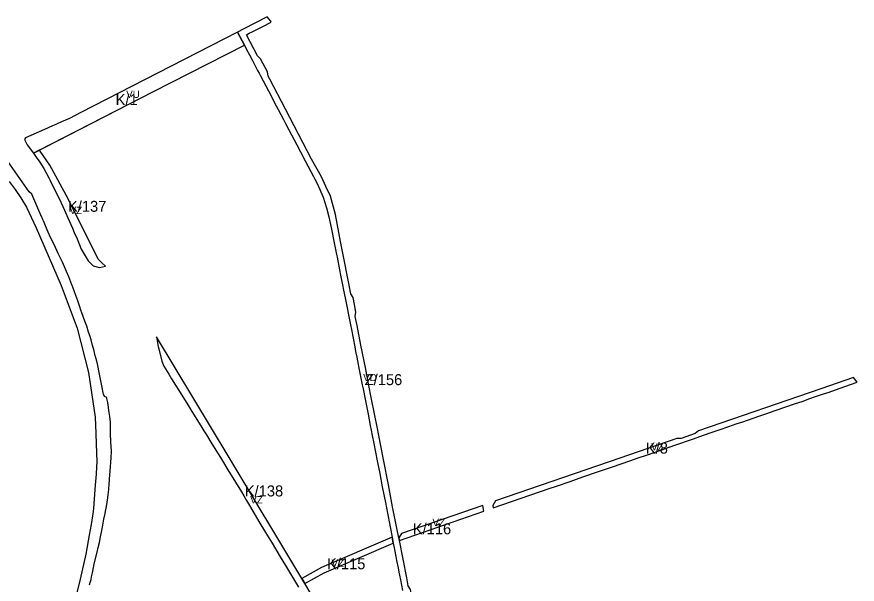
# Model space of a CAD drawing. Extents: x -521939 to -518034, y -1194984 to -1189555.
# Drawn here: x -520886 to -519738, y -1190331 to -1189555 of the extents above; entities that cross this region are included whole.
import ezdxf

# ---------------------------------------------------------------- set-up
doc = ezdxf.new("R2010")
doc.units = 0
for name, color, linetype in [('95420023', 7, 'Continuous'), ('96111023', 7, 'Continuous'), ('96121023', 7, 'Continuous'), ('96141023', 7, 'Continuous'), ('96202223', 7, 'Continuous')]:
    doc.layers.add(name, color=color, linetype=linetype)

msp = doc.modelspace()

# ---------------------------------------------------------------- linework, layer by layer
at = {"layer": '95420023'}
for points in [[(-520363.78, -1190267.42), (-520366.37, -1190254.23), (-520372.66, -1190225.12), (-520377.99, -1190195.02), (-520384.87, -1190160.07), (-520391.56, -1190125.16), (-520393.2, -1190117.89), (-520397.27, -1190097.65), (-520401.22, -1190077.65), (-520405.21, -1190056.77), (-520409.61, -1190034.24), (-520415.58, -1190003.82), (-520420.88, -1189976.82), (-520423.3, -1189964.53), (-520422.41, -1189958.68), (-520424.49, -1189948.09), (-520426.3, -1189938.88), (-520429.34, -1189933.8), (-520431.66, -1189922.07), (-520433.46, -1189912.89), (-520438.94, -1189885.01), (-520443.42, -1189862.15), (-520450.25, -1189825.06), (-520457.28, -1189799.95), (-520463.47, -1189786.79), (-520469.68, -1189773.95), (-520483.13, -1189749.49), (-520518.67, -1189681.41), (-520540.29, -1189640.25), (-520542.46, -1189636.12), (-520543.28, -1189630.26), (-520552.66, -1189612.4), (-520557.02, -1189608.4), (-520572.14, -1189579.59), (-520568.14, -1189577.53), (-520564.14, -1189575.47), (-520555.14, -1189570.83), (-520546.14, -1189566.2), (-520542.1, -1189564.12), (-520538.07, -1189562.04), (-520538.7, -1189561.06), (-520543.9, -1189554.92), (-520576.33, -1189571.62), (-520584.33, -1189575.74)], [(-520584.33, -1189575.74), (-520574.91, -1189593.69)], [(-520574.91, -1189593.69), (-520571.87, -1189599.49), (-520567.98, -1189606.88), (-520563.29, -1189615.69), (-520556.78, -1189628.12), (-520554.77, -1189631.94), (-520552.78, -1189635.77), (-520542.06, -1189656.2), (-520536.5, -1189666.75), (-520533.97, -1189671.56), (-520528.55, -1189681.89), (-520521.58, -1189695.28), (-520518.55, -1189700.78), (-520513.98, -1189709.68), (-520506.96, -1189723.04), (-520503.29, -1189730.03), (-520498.25, -1189739.55), (-520491.89, -1189751.79), (-520480.47, -1189773.36), (-520478.5, -1189777.12), (-520474.96, -1189783.97), (-520467.22, -1189801.74), (-520462.52, -1189816.05), (-520459.4, -1189828.36), (-520457.93, -1189834.89), (-520455.88, -1189845.31), (-520452.13, -1189864.14), (-520448.96, -1189880.06), (-520448.32, -1189883.37), (-520444.85, -1189900.94), (-520443.47, -1189908.13), (-520440.81, -1189921.53), (-520439.37, -1189928.74), (-520437.33, -1189939.01), (-520429.98, -1189976.03), (-520428.73, -1189982.35), (-520424.06, -1190006.15), (-520422.85, -1190012.32), (-520421.24, -1190020.5), (-520418.36, -1190035.16), (-520413.93, -1190058), (-520412.81, -1190063.42), (-520409.99, -1190077.75), (-520405.98, -1190098.21), (-520402.94, -1190113.68), (-520401.68, -1190120.11), (-520400.22, -1190127.57), (-520398.08, -1190138.46), (-520393.44, -1190162.05), (-520389.99, -1190179.56), (-520386.49, -1190197.4), (-520382.22, -1190219.18), (-520379.42, -1190233.48), (-520372.97, -1190266.32)], [(-520868.84, -1189794.27), (-520900.54, -1189748.5)], [(-520896.35, -1189780.16), (-520887.88, -1189790.95), (-520880.21, -1189802.32), (-520872.55, -1189815.19), (-520859.28, -1189843.65), (-520825.3, -1189922.44), (-520803.36, -1189980.65), (-520787.67, -1190041.34), (-520778.83, -1190102.4), (-520777.95, -1190124.57)], [(-520762.83, -1190075.3), (-520766.02, -1190074.02), (-520767.55, -1190070.93), (-520767.88, -1190069.17), (-520769.27, -1190061.72), (-520770.98, -1190052.51), (-520773.22, -1190041.38), (-520775.2, -1190031.58), (-520776.66, -1190025.8), (-520777.88, -1190020.97), (-520778.96, -1190016.65), (-520779.7, -1190013.73), (-520780.76, -1190009.83), (-520782.34, -1190004.2), (-520784.38, -1189996.52), (-520784.78, -1189995.03), (-520785.69, -1189992.16), (-520787.64, -1189985.97), (-520790.16, -1189978), (-520792.63, -1189971.08), (-520794.56, -1189965.83), (-520797.3, -1189958.38), (-520797.68, -1189957.29), (-520800.24, -1189949.98), (-520802.52, -1189943.48), (-520803.82, -1189939.77), (-520805.23, -1189935.82), (-520807.51, -1189929.41), (-520810.03, -1189922.31), (-520810.37, -1189921.35), (-520814.9, -1189910.36), (-520817.79, -1189903.36), (-520820.8, -1189896.58), (-520823.49, -1189890.54), (-520825.65, -1189885.69), (-520829.04, -1189878.62), (-520832.97, -1189870.44), (-520835.85, -1189864.43), (-520839.61, -1189856.58), (-520843.01, -1189849.46), (-520846.54, -1189840.93), (-520849.51, -1189833.76), (-520850.55, -1189831.25), (-520852.17, -1189827.72), (-520852.36, -1189827.29), (-520854.03, -1189823.64), (-520854.32, -1189823.02), (-520865.38, -1189797.27), (-520868.84, -1189794.27)], [(-520762.61, -1190076.58), (-520762.83, -1190075.3)], [(-520760.63, -1190088.46), (-520761.63, -1190082.43), (-520762.61, -1190076.58)], [(-520760.42, -1190089.68), (-520760.63, -1190088.46)], [(-520757.75, -1190120.86), (-520757.85, -1190109.85), (-520757.85, -1190109.21), (-520758.86, -1190101.6), (-520759.61, -1190095.86), (-520760.42, -1190089.68)], [(-520777.95, -1190124.57), (-520777.29, -1190138.74)], [(-520757.68, -1190128.9), (-520757.7, -1190126.98), (-520757.75, -1190120.86)], [(-520756.81, -1190142.53), (-520757.19, -1190136.49), (-520757.5, -1190131.72), (-520757.68, -1190128.9)], [(-520777.29, -1190138.74), (-520776.47, -1190163.36), (-520776.83, -1190170.44)], [(-520756.42, -1190148.49), (-520756.81, -1190142.53)], [(-520756.5, -1190149.9), (-520756.42, -1190148.49)], [(-520757.3, -1190164.53), (-520756.9, -1190157.22)], [(-520756.9, -1190157.22), (-520756.5, -1190149.9)], [(-520776.83, -1190170.44), (-520777.49, -1190180.07)], [(-520758.55, -1190180.97), (-520758.15, -1190176.09), (-520757.6, -1190169.44)], [(-520757.6, -1190169.44), (-520757.3, -1190164.53)], [(-520777.49, -1190180.07), (-520778.53, -1190195.44)], [(-520759.12, -1190187.87), (-520759.06, -1190187.22), (-520758.55, -1190180.97)], [(-520778.53, -1190195.44), (-520780.79, -1190226.94)], [(-520760.72, -1190205.7), (-520760.23, -1190200.24), (-520759.65, -1190193.81)], [(-520759.65, -1190193.81), (-520759.12, -1190187.87)], [(-520760.87, -1190207.48), (-520760.72, -1190205.7)], [(-520765.22, -1190234.17), (-520763.96, -1190228.21), (-520763.7, -1190226.98), (-520762.5, -1190218.73), (-520761.63, -1190212.72), (-520760.87, -1190207.48)], [(-520780.79, -1190226.94), (-520781.3, -1190231.43)], [(-520781.3, -1190231.43), (-520784.36, -1190249.11)], [(-520766.85, -1190241.85), (-520765.22, -1190234.17)], [(-520784.36, -1190249.11), (-520786.83, -1190263.81)], [(-520773, -1190273.46), (-520771.25, -1190266.04), (-520769.69, -1190257.16), (-520768.43, -1190249.96), (-520766.85, -1190241.85)], [(-520786.83, -1190263.81), (-520791.44, -1190289.68)], [(-520776.16, -1190286.78), (-520774.67, -1190280.5), (-520773, -1190273.46)], [(-520372.97, -1190266.32), (-520371.58, -1190274.42)], [(-520371.58, -1190274.42), (-520369.76, -1190283.42), (-520368, -1190292.59), (-520366.87, -1190298.24), (-520364.88, -1190308.35), (-520363.75, -1190314.16), (-520362.96, -1190318.16), (-520361.67, -1190324.78), (-520358.8, -1190339.19)], [(-520363.12, -1190270.76), (-520363.78, -1190267.42)], [(-520260.36, -1190640.4), (-520246.6, -1190614.37), (-520254.03, -1190602.44), (-520256.94, -1190586.97), (-520261.73, -1190576.17), (-520292.37, -1190520.37), (-520305.38, -1190497.4), (-520313.7, -1190481.31), (-520322.01, -1190463.84), (-520328.19, -1190444.19), (-520333.62, -1190421.51), (-520339.48, -1190390.73), (-520343.5, -1190372.52), (-520344.85, -1190363.88), (-520343.97, -1190357.86), (-520345.06, -1190352.29), (-520347.86, -1190338.07), (-520350.9, -1190332.99), (-520352.86, -1190322.18), (-520363.12, -1190270.76)], [(-520780.71, -1190305.7), (-520780.47, -1190304.54), (-520776.16, -1190286.78)], [(-520791.44, -1190289.68), (-520799.14, -1190323.82)], [(-520784.38, -1190324.15), (-520783.68, -1190320.65), (-520782.55, -1190314.95), (-520780.71, -1190305.7)], [(-520799.14, -1190323.82), (-520803.11, -1190340.79), (-520817.75, -1190406.02)], [(-520786.36, -1190331.78), (-520785.46, -1190328.32)], [(-520785.46, -1190328.32), (-520784.38, -1190324.15)]]:
    msp.add_lwpolyline(points, dxfattribs=at)
at = {"layer": '96111023'}
for points in [[(-520584.33, -1189575.74), (-520693.52, -1189631.98), (-520798.15, -1189685.87)], [(-520574.91, -1189593.69), (-520584.33, -1189575.74)], [(-520862.97, -1189741.45), (-520698.86, -1189657.27), (-520574.91, -1189593.69)], [(-520798.15, -1189685.87), (-520813.62, -1189693.84)], [(-520831.59, -1189701.76), (-520832.44, -1189702.13)], [(-520824.7, -1189698.73), (-520831.59, -1189701.76)], [(-520813.62, -1189693.84), (-520824.7, -1189698.73)], [(-520848.1, -1189709.03), (-520873.85, -1189720.38)], [(-520836.95, -1189704.12), (-520848.1, -1189709.03)], [(-520832.44, -1189702.13), (-520836.95, -1189704.12)], [(-520873.85, -1189720.38), (-520875.18, -1189722.65)], [(-520875.18, -1189722.65), (-520871.46, -1189729.85)], [(-520871.46, -1189729.85), (-520862.97, -1189741.45)], [(-520855.05, -1189737.39), (-520862.97, -1189741.45)], [(-520862.97, -1189741.45), (-520859.09, -1189746.74)], [(-520859.09, -1189746.74), (-520854.49, -1189753.78)], [(-520854.52, -1189738.05), (-520855.05, -1189737.39)], [(-520769.62, -1189891.18), (-520774.69, -1189886.48), (-520815.47, -1189803.6), (-520840.73, -1189757.97), (-520853.99, -1189738.71), (-520854.52, -1189738.05)], [(-520854.49, -1189753.78), (-520848.98, -1189762.26)], [(-520848.98, -1189762.26), (-520842.22, -1189775.08)], [(-520842.22, -1189775.08), (-520840.25, -1189778.89)], [(-520840.25, -1189778.89), (-520838.28, -1189782.7)], [(-520838.28, -1189782.7), (-520827.89, -1189803.41)], [(-520827.89, -1189803.41), (-520822.82, -1189814.19)], [(-520822.82, -1189814.19), (-520820.55, -1189819.14)], [(-520820.55, -1189819.14), (-520815.85, -1189829.79)], [(-520815.85, -1189829.79), (-520809.87, -1189843.72)], [(-520809.87, -1189843.72), (-520807.32, -1189849.61)], [(-520807.32, -1189849.61), (-520803.4, -1189858.68)], [(-520803.4, -1189858.68), (-520797.65, -1189872.73)], [(-520797.65, -1189872.73), (-520793.8, -1189879.57)], [(-520793.8, -1189879.57), (-520788.07, -1189888.65)], [(-520788.07, -1189888.65), (-520785.91, -1189890.86)], [(-520785.91, -1189890.86), (-520781.3, -1189895.57), (-520772.63, -1189897.76), (-520764.56, -1189895.88)], [(-520764.56, -1189895.88), (-520769.62, -1189891.18)], [(-520595.57, -1190157.59), (-520694.98, -1189992.45)], [(-520694.98, -1189992.45), (-520692.55, -1190005.5)], [(-520692.55, -1190005.5), (-520691.84, -1190008.79)], [(-520691.84, -1190008.79), (-520687.51, -1190025.96)], [(-520687.51, -1190025.96), (-520685.06, -1190032.49)], [(-520685.06, -1190032.49), (-520678.04, -1190043.73)], [(-520678.04, -1190043.73), (-520674.3, -1190049.78)], [(-520674.3, -1190049.78), (-520668.96, -1190058.36)], [(-519742.92, -1190048.01), (-519787.45, -1190063.39), (-519954.51, -1190121.09), (-519959.21, -1190124.83), (-519978.27, -1190131.41), (-519984.27, -1190131.37), (-520061.95, -1190158.2), (-520231.96, -1190216.92), (-520235.61, -1190223.15)], [(-519762.5, -1190063.2), (-519737.67, -1190054.66)], [(-519737.67, -1190054.66), (-519742.92, -1190048.01)], [(-520668.96, -1190058.36), (-520664.99, -1190064.75), (-520649.81, -1190089.25)], [(-519785.22, -1190071.01), (-519776.17, -1190067.93)], [(-519776.17, -1190067.93), (-519762.5, -1190063.2)], [(-519821.87, -1190083.74), (-519813.04, -1190080.72)], [(-519813.04, -1190080.72), (-519802.38, -1190076.99)], [(-519802.38, -1190076.99), (-519794.41, -1190074.26)], [(-519794.41, -1190074.26), (-519785.22, -1190071.01)], [(-520649.81, -1190089.25), (-520646.54, -1190094.49)], [(-519849.58, -1190093.29), (-519821.87, -1190083.74)], [(-520646.54, -1190094.49), (-520634.26, -1190114.38)], [(-519893.94, -1190108.6), (-519871.89, -1190101.04)], [(-519871.89, -1190101.04), (-519862.6, -1190097.78)], [(-519862.6, -1190097.78), (-519849.58, -1190093.29)], [(-520634.26, -1190114.38), (-520630.08, -1190121.08)], [(-519913.25, -1190115.28), (-519903.02, -1190111.63)], [(-519903.02, -1190111.63), (-519893.94, -1190108.6)], [(-520630.08, -1190121.08), (-520626.81, -1190126.38)], [(-520626.81, -1190126.38), (-520619.25, -1190138.59)], [(-519962.62, -1190132.36), (-519946.2, -1190126.69)], [(-519946.2, -1190126.69), (-519936.96, -1190123.44)], [(-519936.96, -1190123.44), (-519926.15, -1190119.68)], [(-519926.15, -1190119.68), (-519913.25, -1190115.28)], [(-519986.68, -1190140.64), (-519962.62, -1190132.36)], [(-520619.25, -1190138.59), (-520607.45, -1190157.65)], [(-520013.6, -1190149.97), (-519986.68, -1190140.64)], [(-520607.45, -1190157.65), (-520604.7, -1190162.17)], [(-520492.06, -1190329.61), (-520496.15, -1190322.74), (-520595.57, -1190157.59)], [(-520048.21, -1190161.91), (-520036.77, -1190157.93)], [(-520036.77, -1190157.93), (-520024.36, -1190153.64)], [(-520024.36, -1190153.64), (-520013.6, -1190149.97)], [(-520604.7, -1190162.17), (-520597.31, -1190174.18)], [(-520092.49, -1190177.21), (-520071.81, -1190170.12)], [(-520071.81, -1190170.12), (-520060.18, -1190166.05), (-520048.21, -1190161.91)], [(-520597.31, -1190174.18), (-520586.78, -1190191.32)], [(-520129.95, -1190190.13), (-520112.49, -1190184.08)], [(-520112.49, -1190184.08), (-520092.49, -1190177.21)], [(-520586.78, -1190191.32), (-520578.85, -1190204.26)], [(-520148.48, -1190196.56), (-520129.95, -1190190.13)], [(-520578.85, -1190204.26), (-520575.54, -1190209.65)], [(-520235.01, -1190226.44), (-520158.52, -1190200.01)], [(-520158.52, -1190200.01), (-520148.48, -1190196.56)], [(-520575.54, -1190209.65), (-520571.92, -1190216.03)], [(-520571.92, -1190216.03), (-520566.46, -1190225.16)], [(-520566.46, -1190225.16), (-520555.01, -1190244.86)], [(-520249.16, -1190222.86), (-520360.13, -1190261.18), (-520363.78, -1190267.42)], [(-520247.81, -1190230.86), (-520249.16, -1190222.86)], [(-520235.61, -1190223.15), (-520235.01, -1190226.44)], [(-520363.12, -1190270.76), (-520247.81, -1190230.86)], [(-520555.01, -1190244.86), (-520546, -1190259.94)], [(-520546, -1190259.94), (-520537.12, -1190274.8)], [(-520537.12, -1190274.8), (-520525.87, -1190293.08)], [(-520372.97, -1190266.32), (-520469.39, -1190307.83)], [(-520465.85, -1190315.02), (-520371.58, -1190274.42)], [(-520371.58, -1190274.42), (-520372.97, -1190266.32)], [(-520363.78, -1190267.42), (-520363.12, -1190270.76)], [(-520525.87, -1190293.08), (-520518.77, -1190305.18)], [(-520518.77, -1190305.18), (-520505.06, -1190327.7)], [(-520469.39, -1190307.83), (-520496.15, -1190322.74)], [(-520492.06, -1190329.61), (-520465.85, -1190315.02)], [(-520505.06, -1190327.7), (-520500.89, -1190334.53)], [(-520496.15, -1190322.74), (-520492.06, -1190329.61)], [(-520418.63, -1190454.51), (-520492.06, -1190329.61)]]:
    msp.add_lwpolyline(points, dxfattribs=at)
at = {"layer": '96121023'}
for points in [[(-520363.78, -1190267.42), (-520366.37, -1190254.23), (-520372.66, -1190225.12), (-520377.99, -1190195.02), (-520384.87, -1190160.07), (-520391.56, -1190125.16), (-520393.2, -1190117.89), (-520397.27, -1190097.65), (-520401.22, -1190077.65), (-520405.21, -1190056.77), (-520409.61, -1190034.24), (-520415.58, -1190003.82), (-520420.88, -1189976.82), (-520423.3, -1189964.53), (-520422.41, -1189958.68), (-520424.49, -1189948.09), (-520426.3, -1189938.88), (-520429.34, -1189933.8), (-520431.66, -1189922.07), (-520433.46, -1189912.89), (-520438.94, -1189885.01), (-520443.42, -1189862.15), (-520450.25, -1189825.06), (-520457.28, -1189799.95), (-520463.47, -1189786.79), (-520469.68, -1189773.95), (-520483.13, -1189749.49), (-520518.67, -1189681.41), (-520540.29, -1189640.25), (-520542.46, -1189636.12), (-520543.28, -1189630.26), (-520552.66, -1189612.4), (-520557.02, -1189608.4), (-520572.14, -1189579.59), (-520568.14, -1189577.53), (-520564.14, -1189575.47), (-520555.14, -1189570.83), (-520546.14, -1189566.2), (-520542.1, -1189564.12), (-520538.07, -1189562.04), (-520538.7, -1189561.06), (-520543.9, -1189554.92), (-520576.33, -1189571.62), (-520584.33, -1189575.74)], [(-520584.33, -1189575.74), (-520574.91, -1189593.69)], [(-520574.91, -1189593.69), (-520571.87, -1189599.49), (-520567.98, -1189606.88), (-520563.29, -1189615.69), (-520556.78, -1189628.12), (-520554.77, -1189631.94), (-520552.78, -1189635.77), (-520542.06, -1189656.2), (-520536.5, -1189666.75), (-520533.97, -1189671.56), (-520528.55, -1189681.89), (-520521.58, -1189695.28), (-520518.55, -1189700.78), (-520513.98, -1189709.68), (-520506.96, -1189723.04), (-520503.29, -1189730.03), (-520498.25, -1189739.55), (-520491.89, -1189751.79), (-520480.47, -1189773.36), (-520478.5, -1189777.12), (-520474.96, -1189783.97), (-520467.22, -1189801.74), (-520462.52, -1189816.05), (-520459.4, -1189828.36), (-520457.93, -1189834.89), (-520455.88, -1189845.31), (-520452.13, -1189864.14), (-520448.96, -1189880.06), (-520448.32, -1189883.37), (-520444.85, -1189900.94), (-520443.47, -1189908.13), (-520440.81, -1189921.53), (-520439.37, -1189928.74), (-520437.33, -1189939.01), (-520429.98, -1189976.03), (-520428.73, -1189982.35), (-520424.06, -1190006.15), (-520422.85, -1190012.32), (-520421.24, -1190020.5), (-520418.36, -1190035.16), (-520413.93, -1190058), (-520412.81, -1190063.42), (-520409.99, -1190077.75), (-520405.98, -1190098.21), (-520402.94, -1190113.68), (-520401.68, -1190120.11), (-520400.22, -1190127.57), (-520398.08, -1190138.46), (-520393.44, -1190162.05), (-520389.99, -1190179.56), (-520386.49, -1190197.4), (-520382.22, -1190219.18), (-520379.42, -1190233.48), (-520372.97, -1190266.32)], [(-520372.97, -1190266.32), (-520371.58, -1190274.42)], [(-520371.58, -1190274.42), (-520369.76, -1190283.42), (-520368, -1190292.59), (-520366.87, -1190298.24), (-520364.88, -1190308.35), (-520363.75, -1190314.16), (-520362.96, -1190318.16), (-520361.67, -1190324.78), (-520358.8, -1190339.19)], [(-520363.12, -1190270.76), (-520363.78, -1190267.42)], [(-520260.36, -1190640.4), (-520246.6, -1190614.37), (-520254.03, -1190602.44), (-520256.94, -1190586.97), (-520261.73, -1190576.17), (-520292.37, -1190520.37), (-520305.38, -1190497.4), (-520313.7, -1190481.31), (-520322.01, -1190463.84), (-520328.19, -1190444.19), (-520333.62, -1190421.51), (-520339.48, -1190390.73), (-520343.5, -1190372.52), (-520344.85, -1190363.88), (-520343.97, -1190357.86), (-520345.06, -1190352.29), (-520347.86, -1190338.07), (-520350.9, -1190332.99), (-520352.86, -1190322.18), (-520363.12, -1190270.76)]]:
    msp.add_lwpolyline(points, dxfattribs=at)
at = {"layer": '96141023'}
for points in [[(-520584.33, -1189575.74), (-520693.52, -1189631.98), (-520798.15, -1189685.87)], [(-520574.91, -1189593.69), (-520584.33, -1189575.74)], [(-520855.05, -1189737.39), (-520698.86, -1189657.27), (-520574.91, -1189593.69)], [(-520798.15, -1189685.87), (-520813.62, -1189693.84)], [(-520831.59, -1189701.76), (-520832.44, -1189702.13)], [(-520824.7, -1189698.73), (-520831.59, -1189701.76)], [(-520813.62, -1189693.84), (-520824.7, -1189698.73)], [(-520848.1, -1189709.03), (-520873.85, -1189720.38)], [(-520836.95, -1189704.12), (-520848.1, -1189709.03)], [(-520832.44, -1189702.13), (-520836.95, -1189704.12)], [(-520873.85, -1189720.38), (-520875.18, -1189722.65)], [(-520875.18, -1189722.65), (-520871.46, -1189729.85)], [(-520871.46, -1189729.85), (-520862.97, -1189741.45)], [(-520862.97, -1189741.45), (-520855.05, -1189737.39)]]:
    msp.add_lwpolyline(points, dxfattribs=at)
at = {"layer": '96202223'}
for points in [[(-520855.05, -1189737.39), (-520862.97, -1189741.45)], [(-520862.97, -1189741.45), (-520859.09, -1189746.74)], [(-520859.09, -1189746.74), (-520854.49, -1189753.78)], [(-520854.52, -1189738.05), (-520855.05, -1189737.39)], [(-520769.62, -1189891.18), (-520774.69, -1189886.48), (-520815.47, -1189803.6), (-520840.73, -1189757.97), (-520853.99, -1189738.71), (-520854.52, -1189738.05)], [(-520854.49, -1189753.78), (-520848.98, -1189762.26)], [(-520848.98, -1189762.26), (-520842.22, -1189775.08)], [(-520842.22, -1189775.08), (-520840.25, -1189778.89)], [(-520840.25, -1189778.89), (-520838.28, -1189782.7)], [(-520838.28, -1189782.7), (-520827.89, -1189803.41)], [(-520827.89, -1189803.41), (-520822.82, -1189814.19)], [(-520822.82, -1189814.19), (-520820.55, -1189819.14)], [(-520820.55, -1189819.14), (-520815.85, -1189829.79)], [(-520815.85, -1189829.79), (-520809.87, -1189843.72)], [(-520809.87, -1189843.72), (-520807.32, -1189849.61)], [(-520807.32, -1189849.61), (-520803.4, -1189858.68)], [(-520803.4, -1189858.68), (-520797.65, -1189872.73)], [(-520797.65, -1189872.73), (-520793.8, -1189879.57)], [(-520793.8, -1189879.57), (-520788.07, -1189888.65)], [(-520788.07, -1189888.65), (-520785.91, -1189890.86)], [(-520785.91, -1189890.86), (-520781.3, -1189895.57), (-520772.63, -1189897.76), (-520764.56, -1189895.88)], [(-520764.56, -1189895.88), (-520769.62, -1189891.18)], [(-520595.57, -1190157.59), (-520694.98, -1189992.45)], [(-520694.98, -1189992.45), (-520692.55, -1190005.5)], [(-520692.55, -1190005.5), (-520691.84, -1190008.79)], [(-520691.84, -1190008.79), (-520687.51, -1190025.96)], [(-520687.51, -1190025.96), (-520685.06, -1190032.49)], [(-520685.06, -1190032.49), (-520678.04, -1190043.73)], [(-520678.04, -1190043.73), (-520674.3, -1190049.78)], [(-520674.3, -1190049.78), (-520668.96, -1190058.36)], [(-519742.92, -1190048.01), (-519787.45, -1190063.39), (-519954.51, -1190121.09), (-519959.21, -1190124.83), (-519978.27, -1190131.41), (-519984.27, -1190131.37), (-520061.95, -1190158.2), (-520231.96, -1190216.92), (-520235.61, -1190223.15)], [(-519762.5, -1190063.2), (-519737.67, -1190054.66)], [(-519737.67, -1190054.66), (-519742.92, -1190048.01)], [(-520668.96, -1190058.36), (-520664.99, -1190064.75), (-520649.81, -1190089.25)], [(-519785.22, -1190071.01), (-519776.17, -1190067.93)], [(-519776.17, -1190067.93), (-519762.5, -1190063.2)], [(-519821.87, -1190083.74), (-519813.04, -1190080.72)], [(-519813.04, -1190080.72), (-519802.38, -1190076.99)], [(-519802.38, -1190076.99), (-519794.41, -1190074.26)], [(-519794.41, -1190074.26), (-519785.22, -1190071.01)], [(-520649.81, -1190089.25), (-520646.54, -1190094.49)], [(-519849.58, -1190093.29), (-519821.87, -1190083.74)], [(-520646.54, -1190094.49), (-520634.26, -1190114.38)], [(-519893.94, -1190108.6), (-519871.89, -1190101.04)], [(-519871.89, -1190101.04), (-519862.6, -1190097.78)], [(-519862.6, -1190097.78), (-519849.58, -1190093.29)], [(-520634.26, -1190114.38), (-520630.08, -1190121.08)], [(-519913.25, -1190115.28), (-519903.02, -1190111.63)], [(-519903.02, -1190111.63), (-519893.94, -1190108.6)], [(-520630.08, -1190121.08), (-520626.81, -1190126.38)], [(-520626.81, -1190126.38), (-520619.25, -1190138.59)], [(-519962.62, -1190132.36), (-519946.2, -1190126.69)], [(-519946.2, -1190126.69), (-519936.96, -1190123.44)], [(-519936.96, -1190123.44), (-519926.15, -1190119.68)], [(-519926.15, -1190119.68), (-519913.25, -1190115.28)], [(-519986.68, -1190140.64), (-519962.62, -1190132.36)], [(-520619.25, -1190138.59), (-520607.45, -1190157.65)], [(-520013.6, -1190149.97), (-519986.68, -1190140.64)], [(-520607.45, -1190157.65), (-520604.7, -1190162.17)], [(-520496.15, -1190322.74), (-520595.57, -1190157.59)], [(-520048.21, -1190161.91), (-520036.77, -1190157.93)], [(-520036.77, -1190157.93), (-520024.36, -1190153.64)], [(-520024.36, -1190153.64), (-520013.6, -1190149.97)], [(-520604.7, -1190162.17), (-520597.31, -1190174.18)], [(-520092.49, -1190177.21), (-520071.81, -1190170.12)], [(-520071.81, -1190170.12), (-520060.18, -1190166.05), (-520048.21, -1190161.91)], [(-520597.31, -1190174.18), (-520586.78, -1190191.32)], [(-520129.95, -1190190.13), (-520112.49, -1190184.08)], [(-520112.49, -1190184.08), (-520092.49, -1190177.21)], [(-520586.78, -1190191.32), (-520578.85, -1190204.26)], [(-520148.48, -1190196.56), (-520129.95, -1190190.13)], [(-520578.85, -1190204.26), (-520575.54, -1190209.65)], [(-520235.01, -1190226.44), (-520158.52, -1190200.01)], [(-520158.52, -1190200.01), (-520148.48, -1190196.56)], [(-520575.54, -1190209.65), (-520571.92, -1190216.03)], [(-520571.92, -1190216.03), (-520566.46, -1190225.16)], [(-520566.46, -1190225.16), (-520555.01, -1190244.86)], [(-520249.16, -1190222.86), (-520360.13, -1190261.18), (-520363.78, -1190267.42)], [(-520247.81, -1190230.86), (-520249.16, -1190222.86)], [(-520235.61, -1190223.15), (-520235.01, -1190226.44)], [(-520363.12, -1190270.76), (-520247.81, -1190230.86)], [(-520555.01, -1190244.86), (-520546, -1190259.94)], [(-520546, -1190259.94), (-520537.12, -1190274.8)], [(-520537.12, -1190274.8), (-520525.87, -1190293.08)], [(-520372.97, -1190266.32), (-520469.39, -1190307.83)], [(-520465.85, -1190315.02), (-520371.58, -1190274.42)], [(-520371.58, -1190274.42), (-520372.97, -1190266.32)], [(-520363.78, -1190267.42), (-520363.12, -1190270.76)], [(-520525.87, -1190293.08), (-520518.77, -1190305.18)], [(-520518.77, -1190305.18), (-520505.06, -1190327.7)], [(-520469.39, -1190307.83), (-520496.15, -1190322.74)], [(-520492.06, -1190329.61), (-520465.85, -1190315.02)], [(-520505.06, -1190327.7), (-520500.89, -1190334.53)], [(-520492.06, -1190329.61), (-520496.15, -1190322.74)], [(-520496.15, -1190322.74), (-520492.06, -1190329.61)], [(-520418.63, -1190454.51), (-520492.06, -1190329.61)]]:
    msp.add_lwpolyline(points, dxfattribs=at)

# ---------------------------------------------------------------- texts
at = {"layer": '95420023'}
msp.add_text('Z/156', height=15, rotation=0, dxfattribs=at).set_placement((-520410.49, -1190058.54))
at = {"layer": '96111023'}
for s, rotation, p in [('K/1', 0, (-520750.79, -1189675.67)), ('K/137', 0, (-520815.85, -1189821.56)), ('K/8', 360, (-520026.37, -1190152.09)), ('K/138', 360, (-520574.25, -1190210.71)), ('K/116', 360, (-520344.77, -1190262.44)), ('K/115', 360, (-520461.97, -1190310.22))]:
    msp.add_text(s, height=15, rotation=rotation, dxfattribs=at).set_placement(p)
at = {"layer": '96121023'}
msp.add_text('VD', height=10, rotation=360, dxfattribs=at).set_placement((-520412.62, -1190053.09))
at = {"layer": '96141023'}
msp.add_text('VU', height=10, rotation=0, dxfattribs=at).set_placement((-520736.29, -1189665.78))
at = {"layer": '96202223'}
for rotation, p in [(0, (-520813.66, -1189824.73)), (360, (-520019.16, -1190147.89)), (0, (-520317.94, -1190251.25)), (0, (-520455.92, -1190306.81))]:
    msp.add_text('VZ', height=10, rotation=rotation, dxfattribs=at).set_placement(p)
msp.add_text('VZ', height=10, dxfattribs=at).set_placement((-520566.9, -1190220.32))

doc.saveas('drawing.dxf')
